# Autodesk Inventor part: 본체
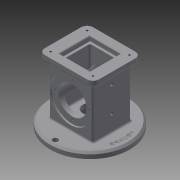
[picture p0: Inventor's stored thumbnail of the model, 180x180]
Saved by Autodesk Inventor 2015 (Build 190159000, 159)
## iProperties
Created: 2019-08
Part Number: 본체
Material: 일반
Document SubType Name: Modeling
Designer: now060
Density: 1 g/cm^3
Appearance: 기본값
Author: now060
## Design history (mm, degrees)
sketch "스케치1"
  geometry: C1 r 67.5 at (0, 0); 1 further point
  constraints: 1 centre point, 1 coincident
  dimensions: "d0" = 135 diameter of C1
extrude "돌출1" new body sketch "스케치1" distance "d1" = 10; taper "d2" = 0 deg
sketch "스케치2"
  geometry: C1 r 67.5 at (0, 0) reference; 3 further points
  constraints: 2 vertical alignment, 1 horizontal alignment
  dimensions: "d3" = 59 distance of C1.centre point (-59, 0); "d4" = 59 distance of C1.centre point (0, 59); "d5" = 59 distance of point (0, -59) C1.centre
hole "구멍1" sketch "스케치2" at (-59, 0), (0, -59), (0, 59) diameter "d6" = 9; stored, may be unused: countersink angle "d10" = 90 deg, drill point angle "d12" = 118 deg; dims "d7" = 6, "d8" = 4, "d9" = 2, "d11" = 8
chamfer "모따기1" distance "d13" = 3; stored, may be unused: second distance "d14" = 2, angle "d15" = 45 deg
sketch "스케치3"
  geometry: C1 r 64.5 at (0, 0) reference; C2 r 59 at (0, 0)
  constraints: 1 centre point, 1 coincident, 1 other
  dimensions: "d16" = 118 diameter of C2
feature "엠보싱1" sketch "스케치3" dims "d17" = 0.5, "d18" = 0
sketch "스케치4"
  geometry: L1 (-37, -33)-(37, -33); L2 (37, -33)-(37, 33); L3 (37, 33)-(-37, 33); L4 (-37, 33)-(-37, -33); C1 r 64.5 at (0, 0) reference
  constraints: 8 end point, 2 parallel, 1 horizontal, 1 perpendicular
  dimensions: "d19" = 74 distance between parallel lines of L4 L2; "d20" = 37 distance from line of L4 C1.centre; "d21" = 66 distance between parallel lines of L3 L1; "d22" = 33 distance from line of L1 C1.centre
extrude "돌출2" join sketch "스케치4" distance "d23" = 88; taper "d24" = 0 deg
sketch "스케치5"
  geometry: L1 (-46, -41)-(46, -41); L2 (46, -41)-(46, 41); L3 (46, 41)-(-46, 41); L4 (-46, 41)-(-46, -41); 1 further point
  constraints: 8 end point, 2 parallel, 1 horizontal, 1 perpendicular
  dimensions: "d25" = 92 distance of L2.end L3.end; "d26" = 46 distance from line of L2 point (0, 0); "d27" = 82 distance between parallel lines of L1 L3; "d28" = 41 distance from line of L1 point (0, 0)
extrude "돌출3" join sketch "스케치5" distance "d29" = 10; taper "d30" = 0 deg
fillet "모깎기1" dims "d31" = 10
sketch "스케치6"
  geometry: A1 r 10 centre (36, 31) between (46, 31) and (36, 41) reference; A2 r 10 centre (-36, 31) between (-36, 41) and (-46, 31) reference; A3 r 10 centre (-36, -31) between (-46, -31) and (-36, -41) reference; A4 r 10 centre (36, -31) between (36, -41) and (46, -31) reference; 1 further point
hole "구멍2" sketch "스케치6" at (-36, -31), (-36, 31), (36, -31), (36, 31) diameter "d32" = 3.242; stored, may be unused: countersink angle "d36" = 90 deg, drill point angle "d38" = 118 deg; dims "d33" = 4, "d34" = 4, "d35" = 2, "d37" = 6
sketch "스케치7"
  geometry: L1 (26, -26)-(-26, -26); L2 (-26, -26)-(-26, 26); L3 (-26, 26)-(26, 26); L4 (26, 26)-(26, -26); L5 (26, -26)-(-26, 26); L6 (-26, -26)-(26, 26); 1 further point
  constraints: 12 end point, 2 midpoint, 2 parallel, 2 perpendicular, 1 horizontal
  dimensions: "d39" = 52 distance of L2.end L3.end
extrude "돌출4" cut sketch "스케치7" distance "d40" = 8; taper "d41" = 0 deg
sketch "스케치8"
  geometry: L1 (22, -22)-(-22, -22); L2 (-22, -22)-(-22, 22); L3 (-22, 22)-(22, 22); L4 (22, 22)-(22, -22); L5 (22, -22)-(-22, 22); L6 (-22, -22)-(22, 22); 1 further point
  constraints: 12 end point, 2 midpoint, 2 parallel, 2 perpendicular, 1 horizontal
  dimensions: "d42" = 44 distance of L2.end L3.end
extrude "돌출5" cut sketch "스케치8" distance "d43" = 74; taper "d44" = 0 deg
fillet "모깎기2" dims "d45" = 3
fillet "모깎기3" dims "d46" = 3
fillet "모깎기4" dims "d47" = 3
fillet "모깎기5" dims "d48" = 3
chamfer "모따기2" distance "d49" = 1; stored, may be unused: second distance "d50" = 2, angle "d51" = 45 deg
sketch "스케치9"
  geometry: L1 (-33.5, -95)-(101.5, -95) reference; C1 r 35 at (34, -41); 1 further point
  constraints: 1 centre point, 1 vertical alignment
  dimensions: "d52" = 70 diameter of C1; "d53" = 54 distance from line of C1.centre L1
extrude "돌출6" cut sketch "스케치9" distance "d54" = 3; taper "d55" = 0 deg
sketch "스케치10"
  geometry: C1 r 35 at (0, 0) reference; 2 further points
  constraints: 1 vertical alignment
  dimensions: "d56" = 29 distance of point (0, 29) C1.centre
hole "구멍3" sketch "스케치10" at (0, 29) diameter "d57" = 3.242; stored, may be unused: countersink angle "d61" = 90 deg, drill point angle "d63" = 118 deg; dims "d58" = 4, "d59" = 4, "d60" = 2, "d62" = 6
sketch "스케치11"
  geometry: C1 r 35 at (0, 0) reference; 1 further point
hole "구멍4" sketch "스케치11" at (0, 0) diameter "d67" = 48; stored, may be unused: countersink angle "d71" = 90 deg, drill point angle "d73" = 118 deg; dims "d68" = 4, "d69" = 4, "d70" = 2, "d72" = 6
sketch "스케치12"
  geometry: C1 r 67.5 at (0, 0) reference
hole "구멍5" sketch "스케치12" at (0, 0) diameter "d74" = 25; stored, may be unused: countersink angle "d78" = 90 deg, drill point angle "d80" = 118 deg; dims "d75" = 4, "d76" = 50, "d77" = 18, "d79" = 6
fillet "모깎기6" dims "d81" = 3
sketch "스케치13"
  geometry: L1 (95, -37.5)-(95, 97.5) reference; 3 further points
  constraints: 2 horizontal alignment
  dimensions: "d82" = 37 distance from line of L1 point (58, 30); "d83" = 43 distance of point (15, 30) point (58, 30)
hole "구멍6" sketch "스케치13" at (15, 30), (58, 30) diameter "d84" = 4.917; stored, may be unused: countersink angle "d88" = 90 deg, drill point angle "d90" = 118 deg; dims "d85" = 12, "d86" = 50, "d87" = 18, "d89" = 48
node "솔리드1"
pattern_circular "원형 패턴1" dims angle "d65" = 360 deg
mirror "대칭1"
